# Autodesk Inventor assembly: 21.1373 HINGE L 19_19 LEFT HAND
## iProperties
Created: 2007-01
Part Number: 21.1373 HINGE L 19_19 LEFT HAND
Document SubType Name: Assembly
Designer: Andy Moles
Mass: 89.2142 g
Surface Area: 154.73 cm^2
Volume: 20.3165 cm^3
Density: 4.39122 g/cm^3
Author: Andy Moles
